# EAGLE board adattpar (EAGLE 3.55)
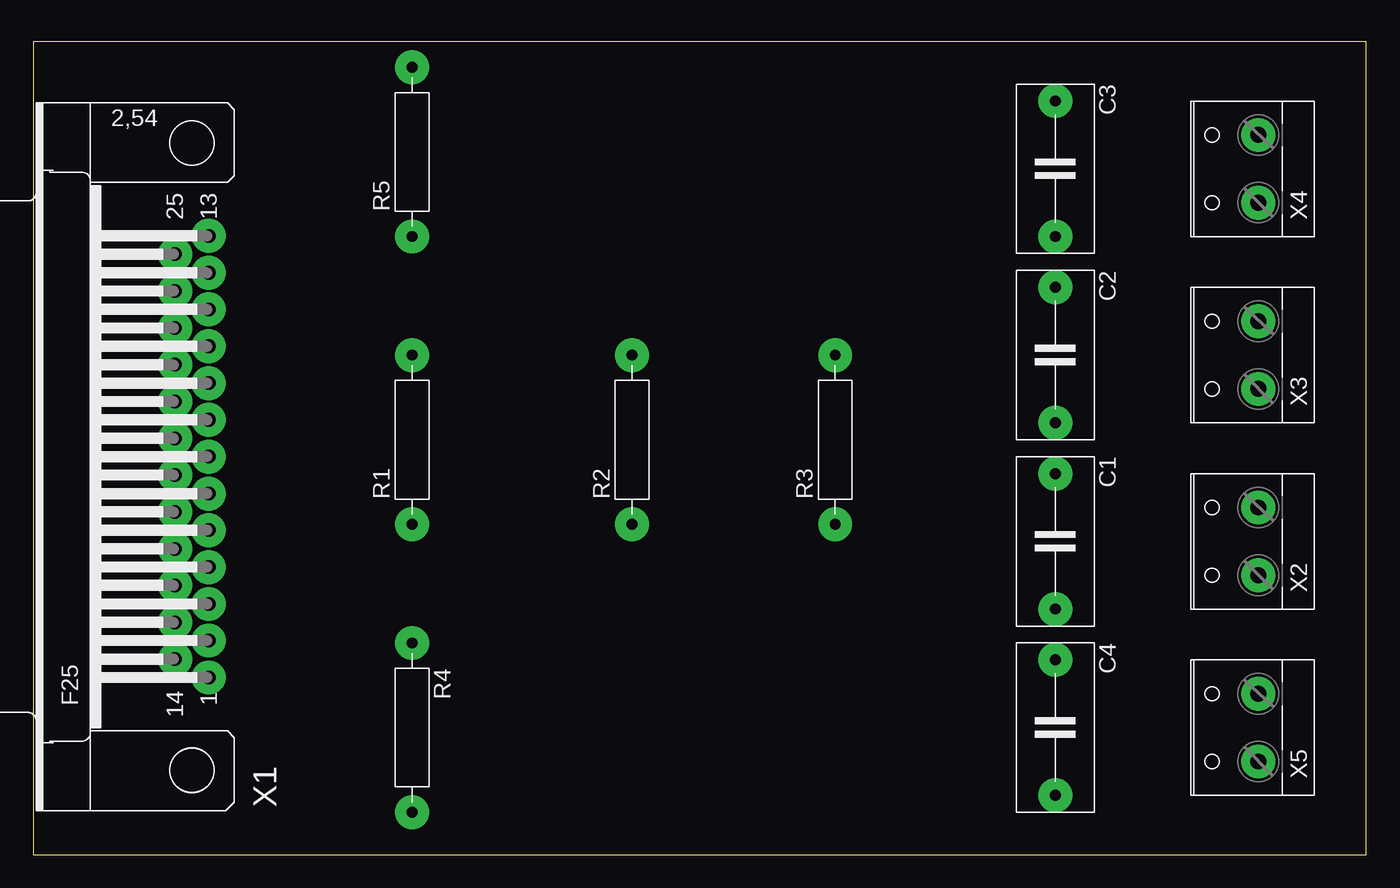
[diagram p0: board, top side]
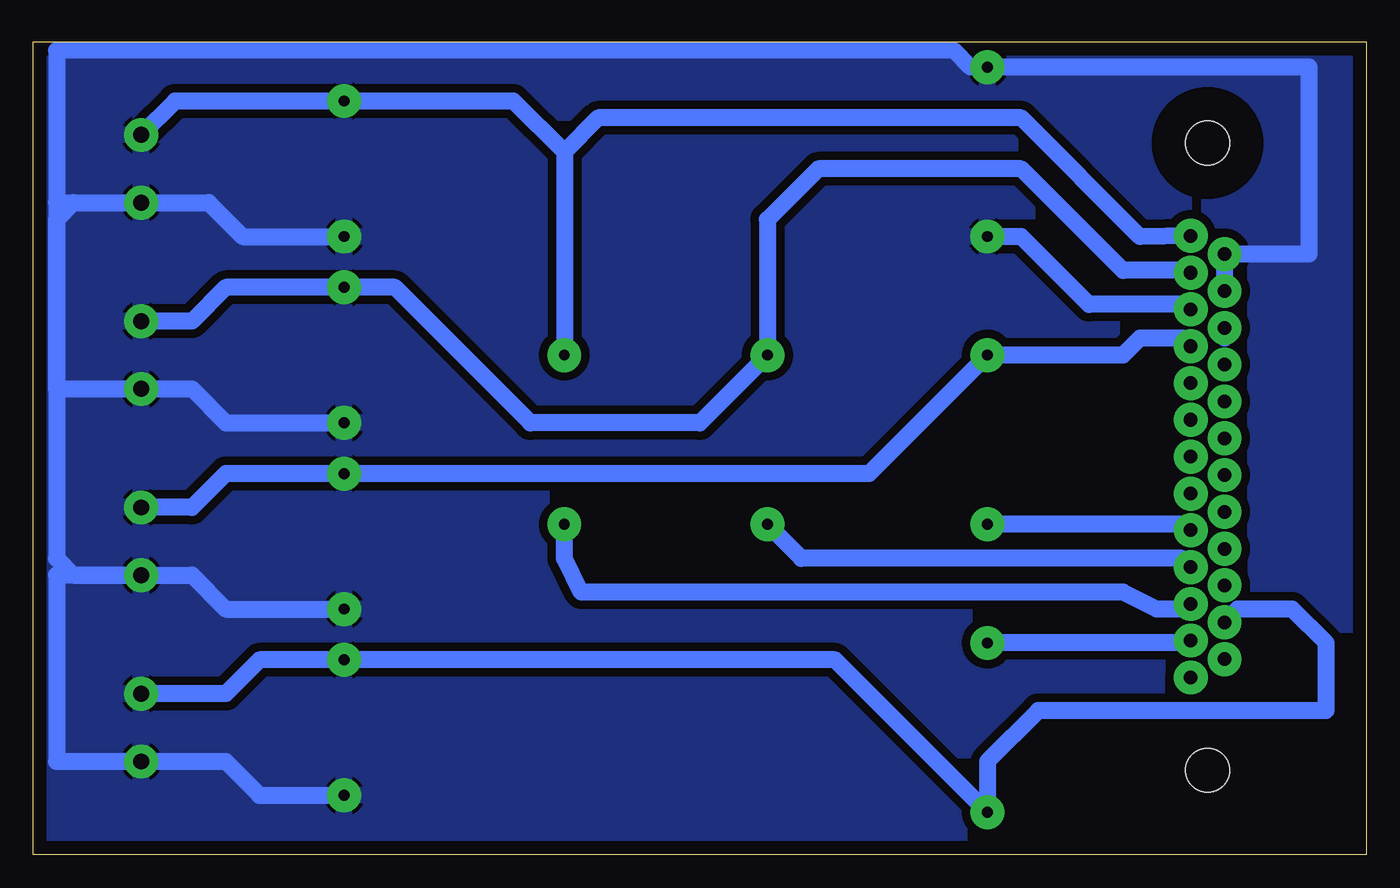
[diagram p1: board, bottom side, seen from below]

Size 100 x 60.95 mm. Coordinates in mm from the lower left corner, seen from the top.
Outline: 0,0 100,0 100,60.95 0,60.95 0,0
Copper layers used: Bottom

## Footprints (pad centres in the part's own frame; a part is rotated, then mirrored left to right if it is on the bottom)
10 = drill 0.813 pad 2.54 round:  -5.08,0;  5.08,0
12,5 = drill 0.813 pad 2.54 round:  -6.35,0;  6.35,0
5H = drill 1.016 pad 2.54 round:  -16.561,-1.27;  -13.792,-1.27;  -11.049,-1.27;  -8.28,-1.27;  -5.512,-1.27;  -2.769,-1.27;  0,-1.27;  2.769,-1.27;  5.512,-1.27;  8.28,-1.27;  11.049,-1.27;  13.792,-1.27;  16.561,-1.27;  -15.189,1.27;  -12.421,1.27;  -9.652,1.27;  -6.909,1.27;  -4.14,1.27;  -1.372,1.27;  1.372,1.27;  4.14,1.27;  6.909,1.27;  9.652,1.27;  12.421,1.27;  15.189,1.27 | hole 3.302: -23.52,0; 23.52,0
37-132 = drill 1.194 pad 2.54 round:  -2.54,0;  2.54,0

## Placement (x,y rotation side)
C1  22nF  [10]  76.67,23.49 270 top
C2  22nF  [10]  76.67,37.46 270 top
C3  22nF  [10]  76.67,51.43 270 top
C4  22nF  [10]  76.67,9.52 270 top
R1  4.7K  [12,5]  28.41,31.11 90 top
R2  4.7K  [12,5]  44.92,31.11 90 top
R3  4.7k  [12,5]  60.16,31.11 90 top
R4  4.7k  [12,5]  28.41,9.52 270 top
R5  100  [12,5]  28.41,52.7 90 top
X1  F25H  [5H]  11.9,29.84 90 top
X2  W237-02P  [37-132]  91.91,23.49 90 top
X3  W237-02P  [37-132]  91.91,37.46 90 top
X4  W237-02P  [37-132]  91.91,51.43 90 top
X5  W237-02P  [37-132]  91.91,9.52 90 top

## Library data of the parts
C1-C4 R1-R5 = discrete
X1 = subd
X2-X5 = wago508

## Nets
GND: C1. C2. C3. C4. R5. X1. X2. X3. X4. X5.
N$1: C1. R1. X1. X2.
N$2: C4. R4. X1. X5.
N$3: R5. X1.
N$4: X1.
N$5: R4. X1.
N$6: R3. X1.
N$7: R2. X1.
N$8: R1. X1.
N$9: X1.
N$10: C2. R2. X1. X3.
N$11: C3. R3. X1. X4.
N$12: X1.
N$14: X1.
N$15: X1.

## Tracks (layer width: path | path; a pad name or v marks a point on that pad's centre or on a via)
GND
  Bottom 1.27: 10.63,42.54 X1. 4.28,45.03 4.28,59.05 R5. 29.68,59.05 30.95,60.32 98.26,60.32 98.26,48.89 | 98.26,48.89 96.99,48.89 | 91.91,48.89 86.83,48.89 84.29,46.35 C3. | 98.26,34.92 98.26,47.62 96.99,48.89 | 96.99,48.89 91.91,48.89 | 91.91,20.95 96.99,20.95 98.26,22.22 98.26,34.92 | 98.26,34.92 91.91,34.92 88.1,34.92 85.56,32.38 C2. | 98.26,48.89 98.26,34.92 | 98.26,48.89 91.91,48.89 | 91.91,20.95 98.26,20.95 98.26,6.98 91.91,6.98 85.56,6.98 83.02,4.44 C4. | C1. 85.56,18.41 88.1,20.95 91.91,20.95
  pour Bottom (isolate 0.635): 0.47,60.32 0.47,0.63 99.53,0.63 99.53,60.32
N$1
  Bottom 1.27: 13.17,38.12 13.78,38.73 16.98,38.73 18.25,37.46 R1. 37.3,28.57 76.67,28.57 85.56,28.57 88.1,26.03 X2.
N$2
  Bottom 1.27: X5. 85.56,12.06 83.02,14.6 76.67,14.6 39.84,14.6 R4. 28.41,6.98 24.6,10.79 3.01,10.79 3.01,15.87 5.55,18.41 9.64,18.41 10.63,17.42
N$3
  Bottom 1.27: 13.17,40.89 13.55,41.27 20.79,41.27 25.87,46.35 28.41,46.35
N$5
  Bottom 1.27: 13.17,16.05 13.35,15.87 28.41,15.87
N$6
  Bottom 1.27: 13.17,18.79 13.55,18.41 15.71,18.41 18.25,19.68 58.89,19.68 60.16,22.22 60.16,24.76
N$7
  Bottom 1.27: 13.17,21.56 13.83,22.22 42.38,22.22 44.92,24.76
N$8
  Bottom 1.27: 13.17,24.33 13.6,24.76 28.41,24.76
N$9
  Bottom 1.27: 10.63,39.49 10.63,38.73
N$10
  Bottom 1.27: 13.17,43.63 13.35,43.81 18.25,43.81 25.87,51.43 41.11,51.43 44.92,47.62 R2. 50,32.38 62.7,32.38 72.86,42.54 76.67,42.54 85.56,42.54 88.1,40 X3.
N$11
  Bottom 1.27: 13.17,46.4 16.98,46.35 25.87,55.24 57.62,55.24 60.16,52.7 | 60.16,52.7 R3. | 60.16,52.7 63.97,56.51 76.67,56.51 89.37,56.51 X4.
N$14
  Bottom 1.27: 10.63,31.21 10.63,31.11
